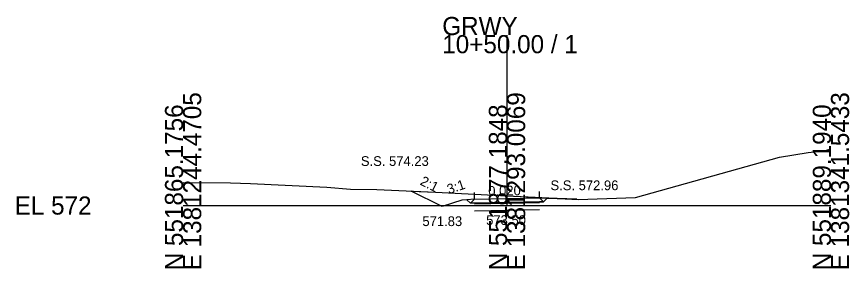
# Model space of a CAD drawing. Extents: x -26 to 103, y -10 to 3028.
# Drawn here: x -25.7 to 102.8, y 490.3 to 529.1 of the extents above; entities that cross this region are included whole.
import ezdxf

# ---------------------------------------------------------------- set-up
doc = ezdxf.new("R2010")
doc.units = 0
for name, color, linetype in [('Exist Cross Section Cell', 7, 'Continuous'), ('Exist XS Center Line Elevation Label', 7, 'Continuous'), ('Exist XS Ground Line', 7, 'Continuous'), ('Prop XS Ditch Slope Text', 7, 'Continuous'), ('Prop XS Ditch Standard Text', 7, 'Continuous'), ('Prop XS Dump Level', 7, 'Continuous'), ('Prop XS Earthwork Shape', 7, 'Continuous'), ('Prop XS EOT Tick Mark', 7, 'Continuous'), ('Prop XS Finish Grade', 7, 'Continuous'), ('Prop XS Finish Grade Earthwork', 7, 'Continuous'), ('Prop XS Finish Grade Pavement', 7, 'Continuous'), ('Prop XS Pvmt Edge Slope', 7, 'Continuous'), ('Prop XS SE Text', 7, 'Continuous'), ('Prop XS Side Slope Text', 7, 'Continuous'), ('Prop XS SS Elevation Text', 7, 'Continuous'), ('Prop XS Subgrade Earthwork', 7, 'Continuous')]:
    doc.layers.add(name, color=color, linetype=linetype)

msp = doc.modelspace()

# ---------------------------------------------------------------- linework, layer by layer
at = {"layer": 'Exist Cross Section Cell'}
for p, q in [((50, 500), (50, 526.3)), ((0, 500), (50, 500)), ((50, 500), (100, 500))]:
    msp.add_line(p, q, dxfattribs=at)
at = {"layer": 'Exist XS Ground Line'}
for p, q in [((92.08, 507.46), (96.49, 508.17)), ((96.49, 508.17), (99.16, 508.49)), ((99.16, 508.49), (100, 508.77)), ((69.83, 501.22), (92.08, 507.46)), ((0, 503.55), (7.34, 503.48)), ((7.34, 503.48), (10.38, 503.41)), ((10.38, 503.41), (22.17, 502.82)), ((22.17, 502.82), (25.83, 502.52)), ((25.83, 502.52), (29.9, 502.48)), ((29.9, 502.48), (38.98, 502.06)), ((38.98, 502.06), (50, 501.5)), ((50, 501.5), (60.99, 500.95)), ((60.99, 500.95), (69.83, 501.22))]:
    msp.add_line(p, q, dxfattribs=at)
at = {"layer": 'Prop XS Dump Level'}
for p, q in [((50, 500.3), (45, 500.2)), ((55, 500.4), (50, 500.3)), ((45, 499.2), (50, 499.3)), ((50, 499.3), (55, 499.4))]:
    msp.add_line(p, q, dxfattribs=at)
at = {"layer": 'Prop XS Earthwork Shape'}
msp.add_lwpolyline([(35.19, 502.23), (38.98, 502.06), (50, 501.5), (60.77, 500.96), (56.18, 501.14), (55.61, 500.58), (55, 500.57), (50, 500.47), (45, 500.37), (44.36, 500.35), (43.82, 500.9), (43, 500.83), (40, 499.83)], close=True, dxfattribs=at)
at = {"layer": 'Prop XS EOT Tick Mark'}
for p, q in [((45, 500.99), (45, 501.99)), ((55, 501.19), (55, 502.19))]:
    msp.add_line(p, q, dxfattribs=at)
at = {"layer": 'Prop XS Finish Grade'}
for p, q in [((45, 500.99), (43.82, 500.9)), ((55, 501.19), (56.18, 501.14))]:
    msp.add_line(p, q, dxfattribs=at)
at = {"layer": 'Prop XS Finish Grade Earthwork'}
for p, q in [((40, 499.83), (35.19, 502.23)), ((43, 500.83), (40, 499.83)), ((43.82, 500.9), (43, 500.83)), ((56.18, 501.14), (60.77, 500.96))]:
    msp.add_line(p, q, dxfattribs=at)
at = {"layer": 'Prop XS Finish Grade Pavement'}
for p, q in [((45, 500.99), (50, 501.09)), ((50, 501.09), (55, 501.19))]:
    msp.add_line(p, q, dxfattribs=at)
at = {"layer": 'Prop XS Pvmt Edge Slope'}
for p, q in [((45, 500.99), (44.36, 500.35)), ((55, 501.19), (55.61, 500.58))]:
    msp.add_line(p, q, dxfattribs=at)
at = {"layer": 'Prop XS Subgrade Earthwork'}
for p, q in [((44.36, 500.35), (43.82, 500.9)), ((45, 500.37), (44.36, 500.35)), ((50, 500.47), (45, 500.37)), ((55, 500.57), (50, 500.47)), ((55, 500.57), (55.61, 500.58)), ((55.61, 500.58), (56.18, 501.14))]:
    msp.add_line(p, q, dxfattribs=at)

# ---------------------------------------------------------------- texts
at = {"layer": 'Exist Cross Section Cell'}
for s, p in [('GRWY', (40, 526.3)), ('10+50.00 / 1', (40, 523.5)), ('EL 572', (-26, 498.6))]:
    msp.add_text(s, height=2.8, dxfattribs=at).set_placement(p)
for s, p in [('E 1381244.4705', (2.8, 490)), ('E 1381293.0069', (52.8, 490)), ('E 1381341.5433', (102.8, 490)), ('N 551865.1756', (0, 490)), ('N 551877.1848', (50, 490)), ('N 551889.1940', (100, 490))]:
    msp.add_text(s, height=2.8, rotation=90, dxfattribs=at).set_placement(p)
at = {"layer": 'Exist XS Center Line Elevation Label'}
msp.add_text('573.50', height=1.5, dxfattribs=at).set_placement((46.78, 497))
at = {"layer": 'Prop XS Ditch Slope Text'}
msp.add_text('3:1', height=1.5, rotation=18.4349, dxfattribs=at).set_placement((41.03, 501.75))
at = {"layer": 'Prop XS Ditch Standard Text'}
msp.add_text('571.83', height=1.5, dxfattribs=at).set_placement((36.94, 496.83))
at = {"layer": 'Prop XS Dump Level'}
for p in [(43, 500), (57, 500.28)]:
    msp.add_text('Case1', height=0.04, dxfattribs=at).set_placement(p)
at = {"layer": 'Prop XS SE Text'}
msp.add_text('0.020', height=1.5, rotation=1.1458, dxfattribs=at).set_placement((47.12, 501.49))
at = {"layer": 'Prop XS Side Slope Text'}
msp.add_text('2:1', height=1.5, rotation=333.4349, dxfattribs=at).set_placement((36.46, 503.28))
at = {"layer": 'Prop XS SS Elevation Text'}
for s, p in [('S.S. 574.23', (27.44, 506.11)), ('S.S. 572.96', (56.71, 502.37))]:
    msp.add_text(s, height=1.5, dxfattribs=at).set_placement(p)

doc.saveas('drawing.dxf')
